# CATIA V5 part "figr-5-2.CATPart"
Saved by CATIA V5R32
Part number: Part1
Bounding box of the stored display mesh (mm): x -23 to 23, y -104 to 104, z 0 to 68
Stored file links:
  D:\PROJECTS\Project 2022\CATIA V5 6R 2022\Resources\Part Files\c05_catia_v5_6r2022_prt\figr-5-2.CATPart
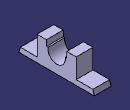
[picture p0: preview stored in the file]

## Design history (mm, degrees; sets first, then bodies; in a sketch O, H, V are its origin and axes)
Sketch1 on yz-plane, origin (0, 0, 0), H (0, 1, 0), V (0, 0, 1)
  line L1 (0, 0) -> (104, 0)
  point P1 (104, 0)
  line L2 (104, 0) -> (100, 14)
  point P2 (100, 14)
  line L3 (100, 14) -> (54, 14)
  point P3 (54, 14)
  line L4 (54, 14) -> (54, 68)
  point P4 (54, 68)
  line L5 (54, 68) -> (28, 68)
  point P5 (28, 68)
  line L6 (28, 68) -> (28, 52)
  point P6 (28, 52)
  line L7 (28, 52) -> (23.6643, 52)
  axis line L8 (0, 0) -> (0, 150)
  point P8 (0, 0)
  construction line L9 through (0, 0) direction (-1, 0)
  construction line L10 through (0, 0) direction (0, 1)
  point P13 (-104, 0)
  point P14 (-100, 14)
  point P15 (-54, 14)
  point P16 (-54, 68)
  point P17 (-28, 68)
  point P18 (-28, 52)
  line L11 (0, 0) -> (-104, 0)
  line L12 (-104, 0) -> (-100, 14)
  line L13 (-100, 14) -> (-54, 14)
  line L14 (-54, 14) -> (-54, 68)
  line L15 (-54, 68) -> (-28, 68)
  line L16 (-28, 68) -> (-28, 52)
  line L17 (-28, 52) -> (-23.6643, 52)
  arc A1 centre (0, 48) radius 24 from (-23.6643, 52) to (23.6643, 52) ccw
  point P19 (0, 48)
  point P20 (13.2665, 68)
  distance P1 P13 = 208
  length L2 V = 14
  length L2 H = 4
  distance L4 L14 = 108
  distance L16 L6 = 56
  distance L1 L5 = 68
  length L6 = 16
  distance P19 L7 = 4
  radius A1 = 24
  horizontal: L1 H, L3 H, L5 H, L7 H
  vertical: L4 V, L6 V, L8 V
  symmetry: O P8 L8, H L9 L8, V L10 L8, P1 P13 L8, P2 P14 L8, P3 P15 L8, P4 P16 L8, P5 P17 L8, P6 P18 L8, L1 L11 L8, L2 L12 L8, L3 L13 L8, L4 L14 L8, L5 L15 L8, L6 L16 L8, L7 L17 L8
  coincidence: P19 L8, A1 P20, P20 L5, O P8
Pad1: profile Sketch1, direction (1, 0, 0), length 23, mirrored extent
Body1 (main body)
